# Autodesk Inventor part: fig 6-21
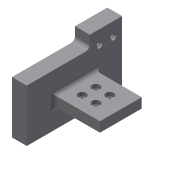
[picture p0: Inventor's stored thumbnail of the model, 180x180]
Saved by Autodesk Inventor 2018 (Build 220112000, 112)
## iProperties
Created: 2004-05
Part Number: fig 6-21
Document SubType Name: Modeling
Designer: CADCIM Technologies
Manufacturer: Standard
Standards Organization: Custom
Density: 1 g/cm^3
Material: Generic
Appearance: Default
Author: CADCIM Technologies
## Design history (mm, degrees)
node "Sketch1"
sketch "Sketch2"
  geometry: L1 (0, 0)-(0, 26.557); L2 (0, 26.557)-(31.986, 26.557); L3 (31.986, 26.557)-(31.986, 32.916); L4 (31.986, 32.916)-(48.42, 32.916); L5 (48.42, 32.916)-(48.42, 0); L6 (48.42, 0)-(0, 0)
  constraints: 12 end point, 4 parallel, 1 perpendicular, 1 vertical
extrude "Extrusion1" new body sketch "Sketch2" distance "d0" = 7.5; taper "d1" = 0 deg
workplane "Work Plane1"
sketch "Sketch3"
  geometry: L1 (7.5, 35.088)-(30.78, 35.088); L2 (30.78, 35.088)-(30.78, 13.871); L3 (30.78, 13.871)-(7.5, 13.871); L4 (7.5, 31.986)-(7.5, 48.42) reference; L5 (7.5, 0)-(7.5, 31.986) reference
  constraints: 6 end point, 2 point on line, 1 horizontal, 1 parallel, 1 perpendicular
extrude "Extrusion2" join sketch "Sketch3" distance "d3" = 5; taper "d4" = 0 deg
fillet "Fillet2" dims "d7" = 2
fillet "Fillet3" dims "d8" = 2
hole "Hole1" diameter "d11" = 3; stored, may be unused: countersink angle "d15" = 90 deg, drill point angle "d17" = 118 deg; dims "d9" = 7, "d10" = 16, "d12" = 6, "d13" = 4, "d14" = 2, "d16" = 8
pattern_linear "Rectangular Pattern1" dims "d20" = 7, "d23" = 7
hole "Hole2" diameter "d26" = 2; stored, may be unused: countersink angle "d30" = 90 deg, drill point angle "d32" = 118 deg; dims "d24" = 5, "d25" = 7, "d27" = 6, "d28" = 3, "d29" = 1, "d31" = 8
pattern_linear "Rectangular Pattern2" dims "d35" = 7
body "Solid1"
other parameters: "d2" = -11
